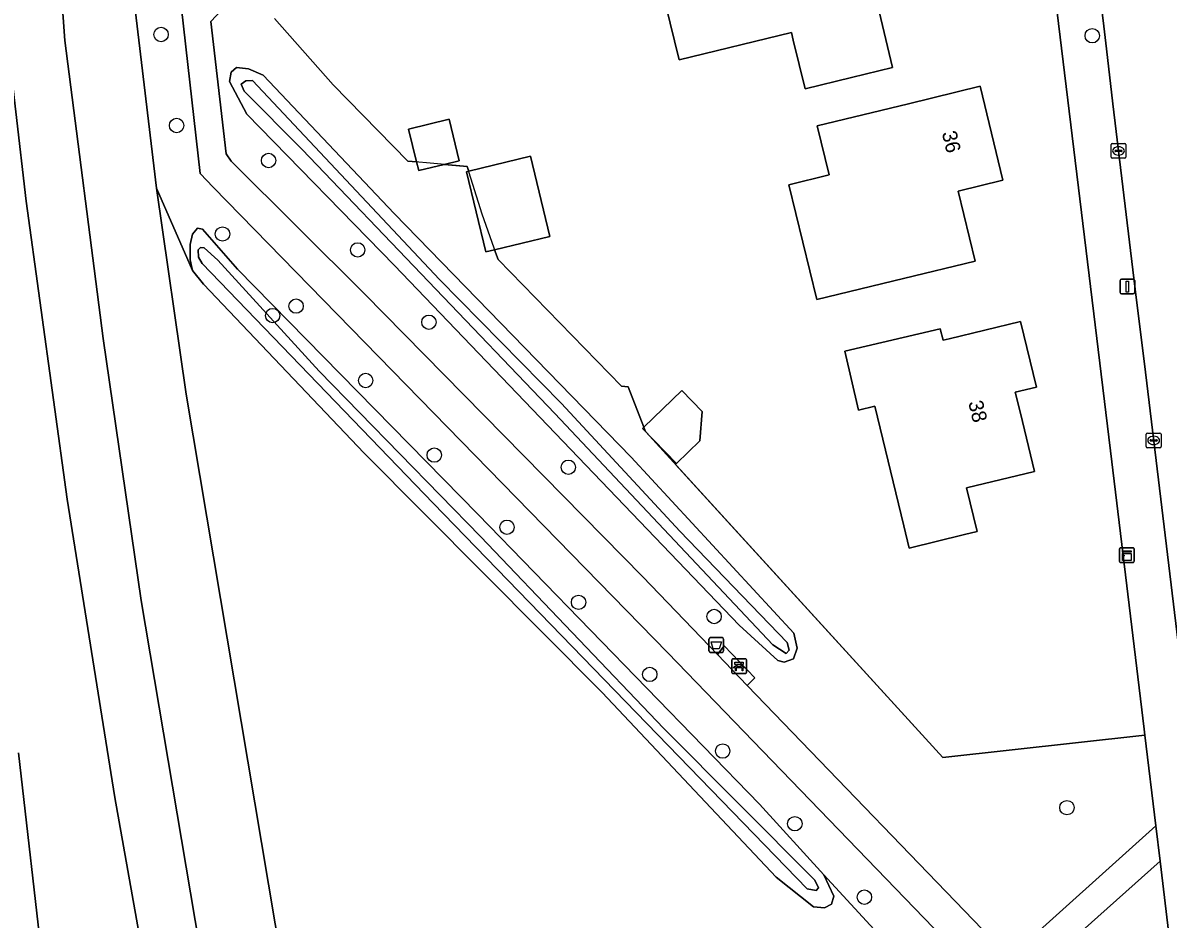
# Model space of a CAD drawing. Extents: x 157648 to 158502, y 379212 to 380938.
# Drawn here: x 158010.4 to 158088.3, y 380404 to 380465 of the extents above; entities that cross this region are included whole.
import ezdxf

# ---------------------------------------------------------------- set-up
doc = ezdxf.new("R2010")
doc.units = 0
for name, color, linetype in [('IMGEO_Afvalbak', 7, 'Continuous'), ('IMGEO_Bank', 7, 'Continuous'), ('IMGEO_Berm_groen', 7, 'Continuous'), ('IMGEO_Boom', 7, 'Continuous'), ('IMGEO_Erf', 7, 'Continuous'), ('IMGEO_Grasland_overig', 7, 'Continuous'), ('IMGEO_Groenvoorziening', 7, 'Continuous'), ('IMGEO_Hek', 7, 'Continuous'), ('IMGEO_Kast', 7, 'Continuous'), ('IMGEO_Kolk', 7, 'Continuous'), ('IMGEO_Lichtmast', 7, 'Continuous'), ('IMGEO_Muur', 7, 'Continuous'), ('IMGEO_Pand', 7, 'Continuous'), ('IMGEO_Pand_nummerreeks', 7, 'Continuous'), ('IMGEO_Rijbaan_lokaal_open', 7, 'Continuous'), ('IMGEO_Voetpad_open', 7, 'Continuous'), ('IMGEO_Waterloop', 7, 'Continuous')]:
    doc.layers.add(name, color=color, linetype=linetype)

msp = doc.modelspace()

# ---------------------------------------------------------------- linework, layer by layer
at = {"layer": 'IMGEO_Afvalbak'}
for p, q in [((158057.024, 380422.24), (158057.024, 380423.04)), ((158057.024, 380423.04), (158057.024, 380422.24)), ((158057.124, 380423.14), (158057.914, 380423.14)), ((158057.914, 380423.14), (158057.124, 380423.14)), ((158058.014, 380423.04), (158058.014, 380422.24)), ((158058.014, 380422.24), (158058.014, 380423.04)), ((158057.914, 380422.14), (158057.124, 380422.14)), ((158057.124, 380422.14), (158057.914, 380422.14))]:
    msp.add_line(p, q, dxfattribs=at)
msp.add_lwpolyline([(158057.167, 380422.854), (158057.871, 380422.854), (158057.722, 380422.384), (158057.316, 380422.384), (158057.167, 380422.854)], dxfattribs=at)
for centre, start, end in [((158057.124, 380423.04), 90, 180), ((158057.124, 380423.04), 90, 180), ((158057.914, 380423.04), 0, 90), ((158057.914, 380423.04), 360, 90), ((158057.124, 380422.24), 180, 270), ((158057.124, 380422.24), 180, 270), ((158057.914, 380422.24), 270, 0), ((158057.914, 380422.24), 270, 0)]:
    msp.add_arc(centre, 0.1, start, end, dxfattribs=at)
at = {"layer": 'IMGEO_Bank'}
for p, q in [((158058.579, 380420.771), (158058.579, 380421.612)), ((158058.579, 380421.612), (158058.579, 380420.771)), ((158058.654, 380421.696), (158059.495, 380421.696)), ((158059.495, 380421.696), (158058.654, 380421.696)), ((158058.888, 380421.202), (158058.888, 380421.308)), ((158058.932, 380421.308), (158058.932, 380421.202)), ((158059.22, 380421.314), (158058.938, 380421.314)), ((158058.938, 380421.196), (158059.22, 380421.196)), ((158059.226, 380421.202), (158059.226, 380421.308)), ((158059.27, 380421.308), (158059.27, 380421.202)), ((158059.579, 380421.621), (158059.579, 380420.78)), ((158059.579, 380420.78), (158059.579, 380421.621)), ((158059.504, 380420.696), (158058.663, 380420.696)), ((158058.663, 380420.696), (158059.504, 380420.696)), ((158059.276, 380421.094), (158058.883, 380421.094))]:
    msp.add_line(p, q, dxfattribs=at)
for points in [[(158058.826, 380421.094), (158058.684, 380421.094), (158058.796, 380421.196), (158058.882, 380421.196)], [(158058.882, 380421.314), (158058.796, 380421.314), (158058.796, 380421.475), (158059.359, 380421.475), (158059.359, 380421.314), (158059.276, 380421.314)], [(158059.276, 380421.196), (158059.359, 380421.196), (158059.471, 380421.094), (158059.332, 380421.094)], [(158058.876, 380421.087), (158058.876, 380420.88), (158058.833, 380420.88), (158058.833, 380421.087)], [(158059.326, 380421.087), (158059.326, 380420.88), (158059.282, 380420.88), (158059.282, 380421.087)]]:
    msp.add_lwpolyline(points, dxfattribs=at)
for centre, radius, start, end in [((158058.657, 380421.618), 0.0779, 92.4484, 184.28452), ((158058.657, 380421.618), 0.0779, 92.4484, 184.28452), ((158058.881, 380421.307), 0.00671, 2.89567, 87.10433), ((158058.881, 380421.203), 0.00671, 272.89567, 357.10433), ((158058.938, 380421.307), 0.00671, 92.89567, 177.10433), ((158058.938, 380421.203), 0.00671, 182.89567, 267.10433), ((158059.22, 380421.307), 0.00671, 2.89567, 87.10433), ((158059.22, 380421.203), 0.00671, 272.89567, 357.10433), ((158059.277, 380421.307), 0.00671, 92.89567, 177.10433), ((158059.277, 380421.203), 0.00671, 182.89567, 267.10433), ((158059.501, 380421.618), 0.0779, 2.4484, 94.28452), ((158059.501, 380421.618), 0.0779, 2.4484, 94.28452), ((158058.657, 380420.774), 0.0779, 182.4484, 274.28452), ((158058.657, 380420.774), 0.0779, 182.4484, 274.28452), ((158058.826, 380421.087), 0.00671, 2.89567, 87.10433), ((158058.883, 380421.087), 0.00671, 92.89567, 177.10433), ((158059.275, 380421.087), 0.00671, 2.89567, 87.10433), ((158059.332, 380421.087), 0.00671, 92.89567, 177.10433), ((158059.501, 380420.774), 0.0779, 272.4484, 4.28452), ((158059.501, 380420.774), 0.0779, 272.4484, 4.28452)]:
    msp.add_arc(centre, radius, start, end, dxfattribs=at)
at = {"layer": 'IMGEO_Berm_groen'}
msp.add_lwpolyline([(158010.041, 380400.64), (158011.015, 380392.665), (158011.989, 380384.691), (158012.983, 380376.699), (158014.029, 380368.746), (158015.095, 380360.776), (158016.196, 380352.825), (158017.264, 380344.819), (158018.473, 380336.91), (158019.632, 380328.926), (158020.859, 380321.018), (158021.993, 380327.86), (158018.465, 380346.617), (158016.093, 380364.988), (158013.468, 380383.677), (158011.757, 380400.444), (158010.079, 380415.304)], dxfattribs=at)
at = {"layer": 'IMGEO_Boom'}
for centre in [(158019.764, 380464.164), (158083.093, 380464.08), (158020.82, 380457.973), (158027.075, 380455.595), (158023.941, 380450.593), (158033.136, 380449.514), (158028.949, 380445.688), (158027.352, 380445.046), (158037.979, 380444.596), (158033.679, 380440.629), (158038.345, 380435.557), (158047.463, 380434.732), (158043.29, 380430.652), (158048.159, 380425.543), (158057.379, 380424.579), (158053.003, 380420.637), (158057.961, 380415.427), (158081.373, 380411.578), (158062.868, 380410.483), (158067.598, 380405.488)]:
    msp.add_circle(centre, 0.489, dxfattribs=at)
at = {"layer": 'IMGEO_Erf'}
msp.add_lwpolyline([(158027.482, 380465.252), (158031.471, 380460.739), (158036.537, 380455.559), (158037.144, 380455.502), (158036.601, 380457.736), (158039.359, 380458.407), (158040.048, 380455.577), (158039.016, 380455.326), (158040.592, 380455.178), (158040.691, 380454.863), (158044.881, 380455.882), (158046.207, 380450.434), (158042.449, 380449.52), (158042.683, 380448.851), (158051.082, 380440.247), (158051.524, 380440.195), (158052.599, 380437.464), (158055.179, 380439.953), (158056.556, 380438.526), (158056.415, 380436.528), (158054.814, 380434.985), (158054.747, 380434.921), (158072.931, 380414.996), (158086.681, 380416.507), (158086.631, 380416.924), (158084.325, 380435.852), (158076.753, 380498.285)], dxfattribs=at)
for points in [[(158071.005, 380479.768), (158072.233, 380474.722), (158071.25, 380474.483), (158071.817, 380472.15), (158070.106, 380471.734), (158071.403, 380466.4), (158068.595, 380465.717), (158069.52, 380461.918), (158066.712, 380461.235), (158063.559, 380460.468), (158062.754, 380463.778), (158062.63, 380464.289), (158054.99, 380462.43), (158051.903, 380475.12), (158054.903, 380475.85), (158061.551, 380477.468), (158066.147, 380478.586)], [(158075.466, 380460.64), (158077.019, 380454.259), (158073.968, 380453.517), (158075.127, 380448.751), (158070.269, 380447.569), (158064.353, 380446.13), (158062.452, 380453.944), (158065.202, 380454.613), (158064.391, 380457.946), (158070.608, 380459.458)], [(158079.312, 380440.181), (158077.863, 380439.828), (158078.208, 380438.411), (158079.172, 380434.446), (158074.552, 380433.322), (158075.272, 380430.36), (158074.403, 380430.148), (158070.649, 380429.234), (158070.279, 380430.753), (158068.303, 380438.877), (158067.2, 380438.622), (158066.266, 380442.629), (158072.761, 380444.144), (158072.95, 380443.368), (158073.366, 380443.469), (158078.224, 380444.651)]]:
    msp.add_lwpolyline(points, close=True, dxfattribs=at)
at = {"layer": 'IMGEO_Grasland_overig'}
for points in [[(158008.456, 380471.073), (158010.584, 380452.82), (158013.374, 380432.56), (158016.624, 380412.267), (158020.638, 380389.734), (158024.366, 380368.251), (158027.936, 380346.578), (158030.204, 380332.282), (158034.696, 380332.931), (158034.982, 380332.972), (158034.323, 380334.52), (158033.486, 380339.124), (158029.884, 380359.089), (158026.37, 380379.535), (158022.37, 380402.161), (158018.402, 380425.669), (158015.817, 380443.497), (158013.211, 380463.747), (158012.888, 380468.466), (158012.716, 380468.453), (158012.032, 380474.96), (158011.103, 380487.525), (158010.246, 380502.882)], [(158010.079, 380415.304), (158011.757, 380400.444), (158013.468, 380383.677), (158016.093, 380364.988), (158018.465, 380346.617), (158021.993, 380327.86), (158030.941, 380327.631), (158030.204, 380332.282), (158027.936, 380346.578), (158024.366, 380368.251), (158020.638, 380389.734), (158016.624, 380412.267), (158013.374, 380432.56), (158010.584, 380452.82), (158008.456, 380471.073)]]:
    msp.add_lwpolyline(points, dxfattribs=at)
at = {"layer": 'IMGEO_Groenvoorziening'}
for points in [[(158074.872, 380400.738), (158054.227, 380422.099), (158023.317, 380453.788), (158022.423, 380454.718), (158021.162, 380465.935), (158023.371, 380468.153), (158024.419, 380469.661), (158026.295, 380471.968), (158026.944, 380473.412), (158027.219, 380474.599), (158027.35, 380476.128), (158027.158, 380477.899), (158024.596, 380487.672), (158020.768, 380504.58), (158017.441, 380518.75), (158016.232, 380525.978), (158016.054, 380527.981), (158016.38, 380532.759)], [(158013.513, 380531.117), (158013.428, 380526.023), (158013.563, 380518.065), (158014.218, 380505.488), (158015.073, 380494.131), (158016.003, 380484.338), (158016.906, 380475.516), (158018.076, 380465.293), (158019.446, 380453.706), (158021.901, 380448.106), (158021.75, 380448.847), (158021.75, 380449.873), (158021.907, 380450.575), (158022.246, 380450.981), (158022.582, 380450.916), (158024.971, 380448.209), (158041.314, 380431.54), (158060.467, 380411.817), (158064.837, 380407.009), (158071.405, 380399.866)], [(158023.153, 380465.044), (158024.181, 380456.051), (158024.539, 380455.555), (158033.6, 380446.522), (158052.528, 380427.284), (158057.599, 380421.983), (158058.058, 380422.588), (158060.148, 380420.401), (158059.616, 380419.875), (158077.461, 380401.381), (158087.42, 380410.342), (158086.681, 380416.507), (158072.931, 380414.996), (158054.747, 380434.921), (158054.814, 380434.985), (158052.508, 380437.376), (158052.599, 380437.464), (158051.524, 380440.195), (158051.082, 380440.247), (158042.683, 380448.851), (158042.449, 380449.52), (158041.861, 380449.377), (158040.536, 380454.825), (158040.691, 380454.863), (158040.592, 380455.178), (158039.016, 380455.326), (158037.289, 380454.906), (158037.144, 380455.502), (158036.537, 380455.559), (158031.471, 380460.739), (158027.482, 380465.252)], [(158071.405, 380399.866), (158064.837, 380407.009), (158065.528, 380405.554), (158065.351, 380405.014), (158064.886, 380404.754), (158064.13, 380404.829), (158061.595, 380406.859), (158049.766, 380419.415), (158033.581, 380435.679), (158022.644, 380447.175), (158021.901, 380448.106), (158019.446, 380453.706), (158021.479, 380439.704), (158028.01, 380400.843)]]:
    msp.add_lwpolyline(points, dxfattribs=at)
for points in [[(158062.773, 380421.709), (158063.034, 380422.418), (158062.804, 380423.435), (158051.734, 380435.421), (158035.627, 380451.982), (158026.714, 380461.388), (158025.703, 380461.837), (158024.891, 380461.928), (158024.539, 380461.599), (158024.421, 380460.97), (158025.607, 380458.749), (158035.643, 380448.459), (158059.072, 380423.978), (158061.715, 380421.586), (158062.142, 380421.478)], [(158051.734, 380435.421), (158062.804, 380423.435), (158063.034, 380422.418), (158062.773, 380421.709), (158062.142, 380421.478), (158061.715, 380421.586), (158059.072, 380423.978), (158035.643, 380448.459), (158025.607, 380458.749), (158024.421, 380460.97), (158024.539, 380461.599), (158024.891, 380461.928), (158025.703, 380461.837), (158026.714, 380461.388), (158035.627, 380451.982)], [(158061.372, 380422.653), (158046.551, 380438.375), (158029.37, 380456.336), (158025.425, 380460.301), (158025.219, 380460.787), (158025.52, 380461.021), (158025.979, 380461.024), (158038.697, 380447.499), (158046.996, 380439.074), (158055.05, 380430.381), (158062.337, 380422.808), (158062.49, 380422.283), (158062.279, 380422.071)], [(158060.467, 380411.817), (158041.314, 380431.54), (158024.971, 380448.209), (158022.582, 380450.916), (158022.246, 380450.981), (158021.907, 380450.575), (158021.75, 380449.873), (158021.75, 380448.847), (158021.901, 380448.106), (158022.644, 380447.175), (158033.581, 380435.679), (158049.766, 380419.415), (158061.595, 380406.859), (158064.13, 380404.829), (158064.886, 380404.754), (158065.351, 380405.014), (158065.528, 380405.554), (158064.837, 380407.009)], [(158064.31, 380405.941), (158063.717, 380406.06), (158038.281, 380432.283), (158022.558, 380448.594), (158022.313, 380449.025), (158022.286, 380449.523), (158022.445, 380449.67), (158022.695, 380449.655), (158023.618, 380448.807), (158030.525, 380441.266), (158041.488, 380430.009), (158053.964, 380416.969), (158064.222, 380406.634), (158064.485, 380406.114)], [(158087.71, 380407.928), (158078.805, 380399.971), (158090.083, 380388.142)]]:
    msp.add_lwpolyline(points, close=True, dxfattribs=at)
at = {"layer": 'IMGEO_Hek'}
msp.add_lwpolyline([(158086.631, 380416.924), (158084.325, 380435.852)], dxfattribs=at)
at = {"layer": 'IMGEO_Kast'}
for p, q in [((158084.951, 380428.33), (158084.951, 380429.171)), ((158084.951, 380429.171), (158084.951, 380428.33)), ((158085.026, 380429.255), (158085.867, 380429.255)), ((158085.867, 380429.255), (158085.026, 380429.255)), ((158085.951, 380429.18), (158085.951, 380428.339)), ((158085.951, 380428.339), (158085.951, 380429.18)), ((158085.876, 380428.255), (158085.035, 380428.255)), ((158085.035, 380428.255), (158085.876, 380428.255))]:
    msp.add_line(p, q, dxfattribs=at)
for points in [[(158085.146, 380429.045), (158085.746, 380429.045), (158085.746, 380428.96), (158085.146, 380428.96), (158085.146, 380429.045)], [(158085.146, 380428.87), (158085.746, 380428.87), (158085.746, 380428.381), (158085.146, 380428.381), (158085.146, 380428.87)]]:
    msp.add_lwpolyline(points, dxfattribs=at)
msp.add_circle((158085.23, 380428.719), 0.0377, dxfattribs=at)
for centre, start, end in [((158085.029, 380429.177), 92.4484, 184.28452), ((158085.029, 380429.177), 92.4484, 184.28452), ((158085.873, 380429.177), 2.4484, 94.28452), ((158085.873, 380429.177), 2.4484, 94.28452), ((158085.029, 380428.333), 182.4484, 274.28452), ((158085.029, 380428.333), 182.4484, 274.28452), ((158085.873, 380428.333), 272.4484, 4.28452), ((158085.873, 380428.333), 272.4484, 4.28452)]:
    msp.add_arc(centre, 0.0779, start, end, dxfattribs=at)
at = {"layer": 'IMGEO_Kolk'}
for p, q in [((158084.378, 380455.82), (158084.378, 380456.672)), ((158084.453, 380456.746), (158085.305, 380456.746)), ((158084.637, 380456.24), (158084.637, 380456.252)), ((158084.68, 380456.289), (158085.078, 380456.289)), ((158084.866, 380456.526), (158084.891, 380456.526)), ((158085.121, 380456.252), (158085.121, 380456.24)), ((158085.379, 380456.672), (158085.379, 380455.82)), ((158085.305, 380455.746), (158084.453, 380455.746)), ((158085.075, 380456.203), (158084.677, 380456.203)), ((158084.889, 380455.966), (158084.864, 380455.966)), ((158086.772, 380436.131), (158086.772, 380436.983)), ((158086.847, 380437.057), (158087.699, 380437.057)), ((158087.26, 380436.837), (158087.285, 380436.837)), ((158087.773, 380436.983), (158087.773, 380436.131)), ((158087.699, 380436.057), (158086.847, 380436.057)), ((158087.031, 380436.551), (158087.031, 380436.563)), ((158087.469, 380436.514), (158087.071, 380436.514)), ((158087.074, 380436.6), (158087.472, 380436.6)), ((158087.283, 380436.277), (158087.258, 380436.277)), ((158087.515, 380436.563), (158087.515, 380436.551))]:
    msp.add_line(p, q, dxfattribs=at)
for points in [[(158084.378, 380455.82), (158084.378, 380456.672)], [(158084.453, 380456.746), (158085.305, 380456.746)], [(158085.379, 380456.672), (158085.379, 380455.82)], [(158085.305, 380455.746), (158084.453, 380455.746)], [(158086.772, 380436.131), (158086.772, 380436.983)], [(158086.847, 380437.057), (158087.699, 380437.057)], [(158087.773, 380436.983), (158087.773, 380436.131)], [(158087.699, 380436.057), (158086.847, 380436.057)]]:
    msp.add_lwpolyline(points, dxfattribs=at)
for centre, radius, start, end in [((158084.455, 380456.67), 0.0765, 91.55205, 178.44795), ((158084.455, 380456.67), 0.0765, 91.55205, 178.44795), ((158084.677, 380456.249), 0.0403, 85.87752, 175.75265), ((158084.674, 380456.239), 0.0366, 178.93798, 274.71019), ((158085.078, 380456.246), 0.043, 264.86636, 352.45326), ((158085.082, 380456.251), 0.0386, 1.73085, 96.63898), ((158085.303, 380456.67), 0.0765, 1.55205, 88.44795), ((158085.303, 380456.67), 0.0765, 1.55205, 88.44795), ((158084.455, 380455.822), 0.0765, 181.55205, 268.44795), ((158084.455, 380455.822), 0.0765, 181.55205, 268.44795), ((158085.303, 380455.822), 0.0765, 271.55205, 358.44795), ((158085.303, 380455.822), 0.0765, 271.55205, 358.44795), ((158086.849, 380436.981), 0.0765, 91.55205, 178.44795), ((158086.849, 380436.981), 0.0765, 91.55205, 178.44795), ((158087.697, 380436.981), 0.0765, 1.55205, 88.44795), ((158087.697, 380436.981), 0.0765, 1.55205, 88.44795), ((158086.849, 380436.133), 0.0765, 181.55205, 268.44795), ((158086.849, 380436.133), 0.0765, 181.55205, 268.44795), ((158087.071, 380436.56), 0.0403, 85.87752, 175.75265), ((158087.068, 380436.55), 0.0366, 178.93798, 274.71019), ((158087.472, 380436.557), 0.043, 264.86636, 352.45326), ((158087.476, 380436.562), 0.0386, 1.73085, 96.63898), ((158087.697, 380436.133), 0.0765, 271.55205, 358.44795), ((158087.697, 380436.133), 0.0765, 271.55205, 358.44795)]:
    msp.add_arc(centre, radius, start, end, dxfattribs=at)
for centre, major_axis, ratio, start_param, end_param in [((158084.865, 380456.246), (-0.387, 0.002), 0.722429, 4.712389, 7.853982), ((158084.89, 380456.246), (-0.39, 0.002), 0.717154, 1.570796, 4.712389), ((158087.259, 380436.557), (-0.387, 0.002), 0.722429, 4.712389, 7.853982), ((158087.284, 380436.557), (-0.39, 0.002), 0.717154, 1.570796, 4.712389)]:
    msp.add_ellipse(centre, major_axis=major_axis, ratio=ratio, start_param=start_param, end_param=end_param, dxfattribs=at)
at = {"layer": 'IMGEO_Lichtmast'}
for p, q in [((158084.992, 380446.622), (158084.992, 380447.422)), ((158084.992, 380447.422), (158084.992, 380446.622)), ((158085.092, 380447.522), (158085.882, 380447.522)), ((158085.882, 380447.522), (158085.092, 380447.522)), ((158085.982, 380447.422), (158085.982, 380446.622)), ((158085.982, 380446.622), (158085.982, 380447.422)), ((158085.882, 380446.522), (158085.092, 380446.522)), ((158085.092, 380446.522), (158085.882, 380446.522))]:
    msp.add_line(p, q, dxfattribs=at)
msp.add_lwpolyline([(158085.412, 380447.397), (158085.562, 380447.397), (158085.562, 380446.647), (158085.412, 380446.647), (158085.412, 380447.397)], dxfattribs=at)
for centre, start, end in [((158085.092, 380447.422), 90, 180), ((158085.092, 380447.422), 90, 180), ((158085.882, 380447.422), 0, 90), ((158085.882, 380447.422), 360, 90), ((158085.092, 380446.622), 180, 270), ((158085.092, 380446.622), 180, 270), ((158085.882, 380446.622), 270, 0), ((158085.882, 380446.622), 270, 0)]:
    msp.add_arc(centre, 0.1, start, end, dxfattribs=at)
at = {"layer": 'IMGEO_Muur'}
msp.add_lwpolyline([(158086.681, 380416.507), (158072.931, 380414.996), (158052.73, 380437.131), (158051.524, 380440.195), (158051.082, 380440.247), (158042.683, 380448.851), (158041.604, 380451.94), (158040.592, 380455.178), (158036.537, 380455.559), (158031.471, 380460.739), (158027.482, 380465.252)], dxfattribs=at)
at = {"layer": 'IMGEO_Pand'}
for points in [[(158070.106, 380471.734), (158071.817, 380472.15), (158071.25, 380474.483), (158072.233, 380474.722), (158071.005, 380479.768), (158066.147, 380478.586), (158061.551, 380477.468), (158054.903, 380475.85), (158051.903, 380475.12), (158054.99, 380462.43), (158062.63, 380464.289), (158062.754, 380463.778), (158063.559, 380460.468), (158066.712, 380461.235), (158069.52, 380461.918), (158068.595, 380465.717), (158071.403, 380466.4)], [(158062.452, 380453.944), (158064.353, 380446.13), (158070.269, 380447.569), (158075.127, 380448.751), (158073.968, 380453.517), (158077.019, 380454.259), (158075.466, 380460.64), (158070.608, 380459.458), (158064.391, 380457.946), (158065.202, 380454.613)], [(158037.144, 380455.502), (158037.289, 380454.906), (158039.016, 380455.326), (158040.048, 380455.577), (158039.359, 380458.407), (158036.601, 380457.736)], [(158040.691, 380454.863), (158040.536, 380454.825), (158041.861, 380449.377), (158042.449, 380449.52), (158046.207, 380450.434), (158044.881, 380455.882)], [(158078.208, 380438.411), (158077.863, 380439.828), (158079.312, 380440.181), (158078.224, 380444.651), (158073.366, 380443.469), (158072.95, 380443.368), (158072.761, 380444.144), (158066.266, 380442.629), (158067.2, 380438.622), (158068.303, 380438.877), (158070.279, 380430.753), (158070.649, 380429.234), (158074.403, 380430.148), (158075.272, 380430.36), (158074.552, 380433.322), (158079.172, 380434.446)], [(158056.556, 380438.526), (158055.179, 380439.953), (158052.599, 380437.464), (158052.508, 380437.376), (158054.814, 380434.985), (158056.415, 380436.528)]]:
    msp.add_lwpolyline(points, close=True, dxfattribs=at)
at = {"layer": 'IMGEO_Rijbaan_lokaal_open'}
msp.add_lwpolyline([(158088.547, 380482.967), (158088.09, 380486.736), (158086.903, 380496.686), (158086.439, 380500.445), (158085.198, 380510.659), (158084.741, 380514.431), (158082.958, 380529.523), (158076.245, 380528.73), (158077.715, 380516.353), (158078.254, 380511.803), (158079.926, 380497.842), (158080.477, 380493.331), (158081.782, 380482.399), (158082.23, 380478.604), (158083.435, 380468.487), (158083.878, 380464.74), (158084.064, 380463.2), (158084.501, 380459.454), (158086.089, 380446.282), (158086.642, 380441.77), (158091.201, 380403.997)], dxfattribs=at)
at = {"layer": 'IMGEO_Voetpad_open'}
for points in [[(158016.38, 380532.759), (158016.054, 380527.981), (158016.232, 380525.978), (158017.441, 380518.75), (158020.768, 380504.58), (158024.596, 380487.672), (158027.158, 380477.899), (158027.35, 380476.128), (158027.219, 380474.599), (158026.944, 380473.412), (158026.295, 380471.968), (158024.419, 380469.661), (158023.371, 380468.153), (158021.162, 380465.935), (158022.423, 380454.718), (158023.317, 380453.788), (158054.227, 380422.099), (158074.872, 380400.738)], [(158091.201, 380403.997), (158086.642, 380441.77), (158086.089, 380446.282), (158084.501, 380459.454), (158084.064, 380463.2), (158083.878, 380464.74), (158083.435, 380468.487), (158082.23, 380478.604), (158081.782, 380482.399), (158080.477, 380493.331), (158079.926, 380497.842), (158078.254, 380511.803), (158077.715, 380516.353), (158076.245, 380528.73), (158076.07, 380533.27)], [(158078.805, 380399.971), (158087.71, 380407.928), (158087.42, 380410.342), (158077.461, 380401.381), (158059.616, 380419.875), (158057.599, 380421.983), (158052.528, 380427.284), (158033.6, 380446.522), (158024.539, 380455.555), (158024.181, 380456.051), (158023.153, 380465.044), (158024.22, 380466.173), (158029.089, 380471.859), (158029.439, 380473.013), (158029.675, 380474.657), (158029.27, 380477.483), (158026.659, 380487.511), (158019.073, 380520.078), (158018.371, 380523.767), (158018.149, 380525.829), (158018.049, 380530.053), (158018.258, 380532.115)], [(158073.063, 380528.837), (158074.678, 380515.405), (158076.753, 380498.285), (158084.325, 380435.852), (158086.631, 380416.924), (158086.681, 380416.507), (158087.42, 380410.342), (158087.71, 380407.928), (158090.083, 380388.142), (158090.472, 380384.897), (158090.592, 380383.892), (158109.224, 380364.626), (158111.192, 380366.685), (158093.226, 380385.279), (158095.545, 380387.499), (158113.544, 380368.914), (158113.647, 380369.012), (158113.548, 380369.117), (158113.871, 380369.425), (158099.931, 380383.806)]]:
    msp.add_lwpolyline(points, dxfattribs=at)
msp.add_lwpolyline([(158059.616, 380419.875), (158060.148, 380420.401), (158058.058, 380422.588), (158057.599, 380421.983)], close=True, dxfattribs=at)
at = {"layer": 'IMGEO_Waterloop'}
for points in [[(158010.981, 380533.418), (158010.715, 380526.098), (158010.407, 380517.662), (158010.912, 380501.977), (158011.799, 380484.364), (158012.888, 380468.466), (158013.211, 380463.747), (158015.817, 380443.497), (158018.402, 380425.669), (158022.37, 380402.161)], [(158028.01, 380400.843), (158021.479, 380439.704), (158019.446, 380453.706), (158018.076, 380465.293), (158016.906, 380475.516), (158016.003, 380484.338), (158015.073, 380494.131), (158014.218, 380505.488), (158013.563, 380518.065), (158013.428, 380526.023), (158013.513, 380531.117)]]:
    msp.add_lwpolyline(points, dxfattribs=at)
for points in [[(158062.279, 380422.071), (158062.49, 380422.283), (158062.337, 380422.808), (158055.05, 380430.381), (158046.996, 380439.074), (158038.697, 380447.499), (158025.979, 380461.024), (158025.52, 380461.021), (158025.219, 380460.787), (158025.425, 380460.301), (158029.37, 380456.336), (158046.551, 380438.375), (158061.372, 380422.653)], [(158064.485, 380406.114), (158064.222, 380406.634), (158053.964, 380416.969), (158041.488, 380430.009), (158030.525, 380441.266), (158023.618, 380448.807), (158022.695, 380449.655), (158022.445, 380449.67), (158022.286, 380449.523), (158022.313, 380449.025), (158022.558, 380448.594), (158038.281, 380432.283), (158063.717, 380406.06), (158064.31, 380405.941)]]:
    msp.add_lwpolyline(points, close=True, dxfattribs=at)

# ---------------------------------------------------------------- texts
at = {"layer": 'IMGEO_Pand_nummerreeks'}
for s, rotation, p in [('36', 283.67629, (158072.86, 380457.477)), ('38', 283.68202, (158074.654, 380439.143))]:
    msp.add_text(s, height=1, rotation=rotation, dxfattribs=at).set_placement(p)

doc.saveas('drawing.dxf')
